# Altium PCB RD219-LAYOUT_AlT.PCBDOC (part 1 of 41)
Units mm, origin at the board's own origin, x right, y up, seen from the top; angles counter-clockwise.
Board outline 209.75 x 159.97 mm, 2 copper layers (TOP, BOTTOM), stack 0 mm thick; 398 components, 199 nets, 1469 pads, 0 vias.
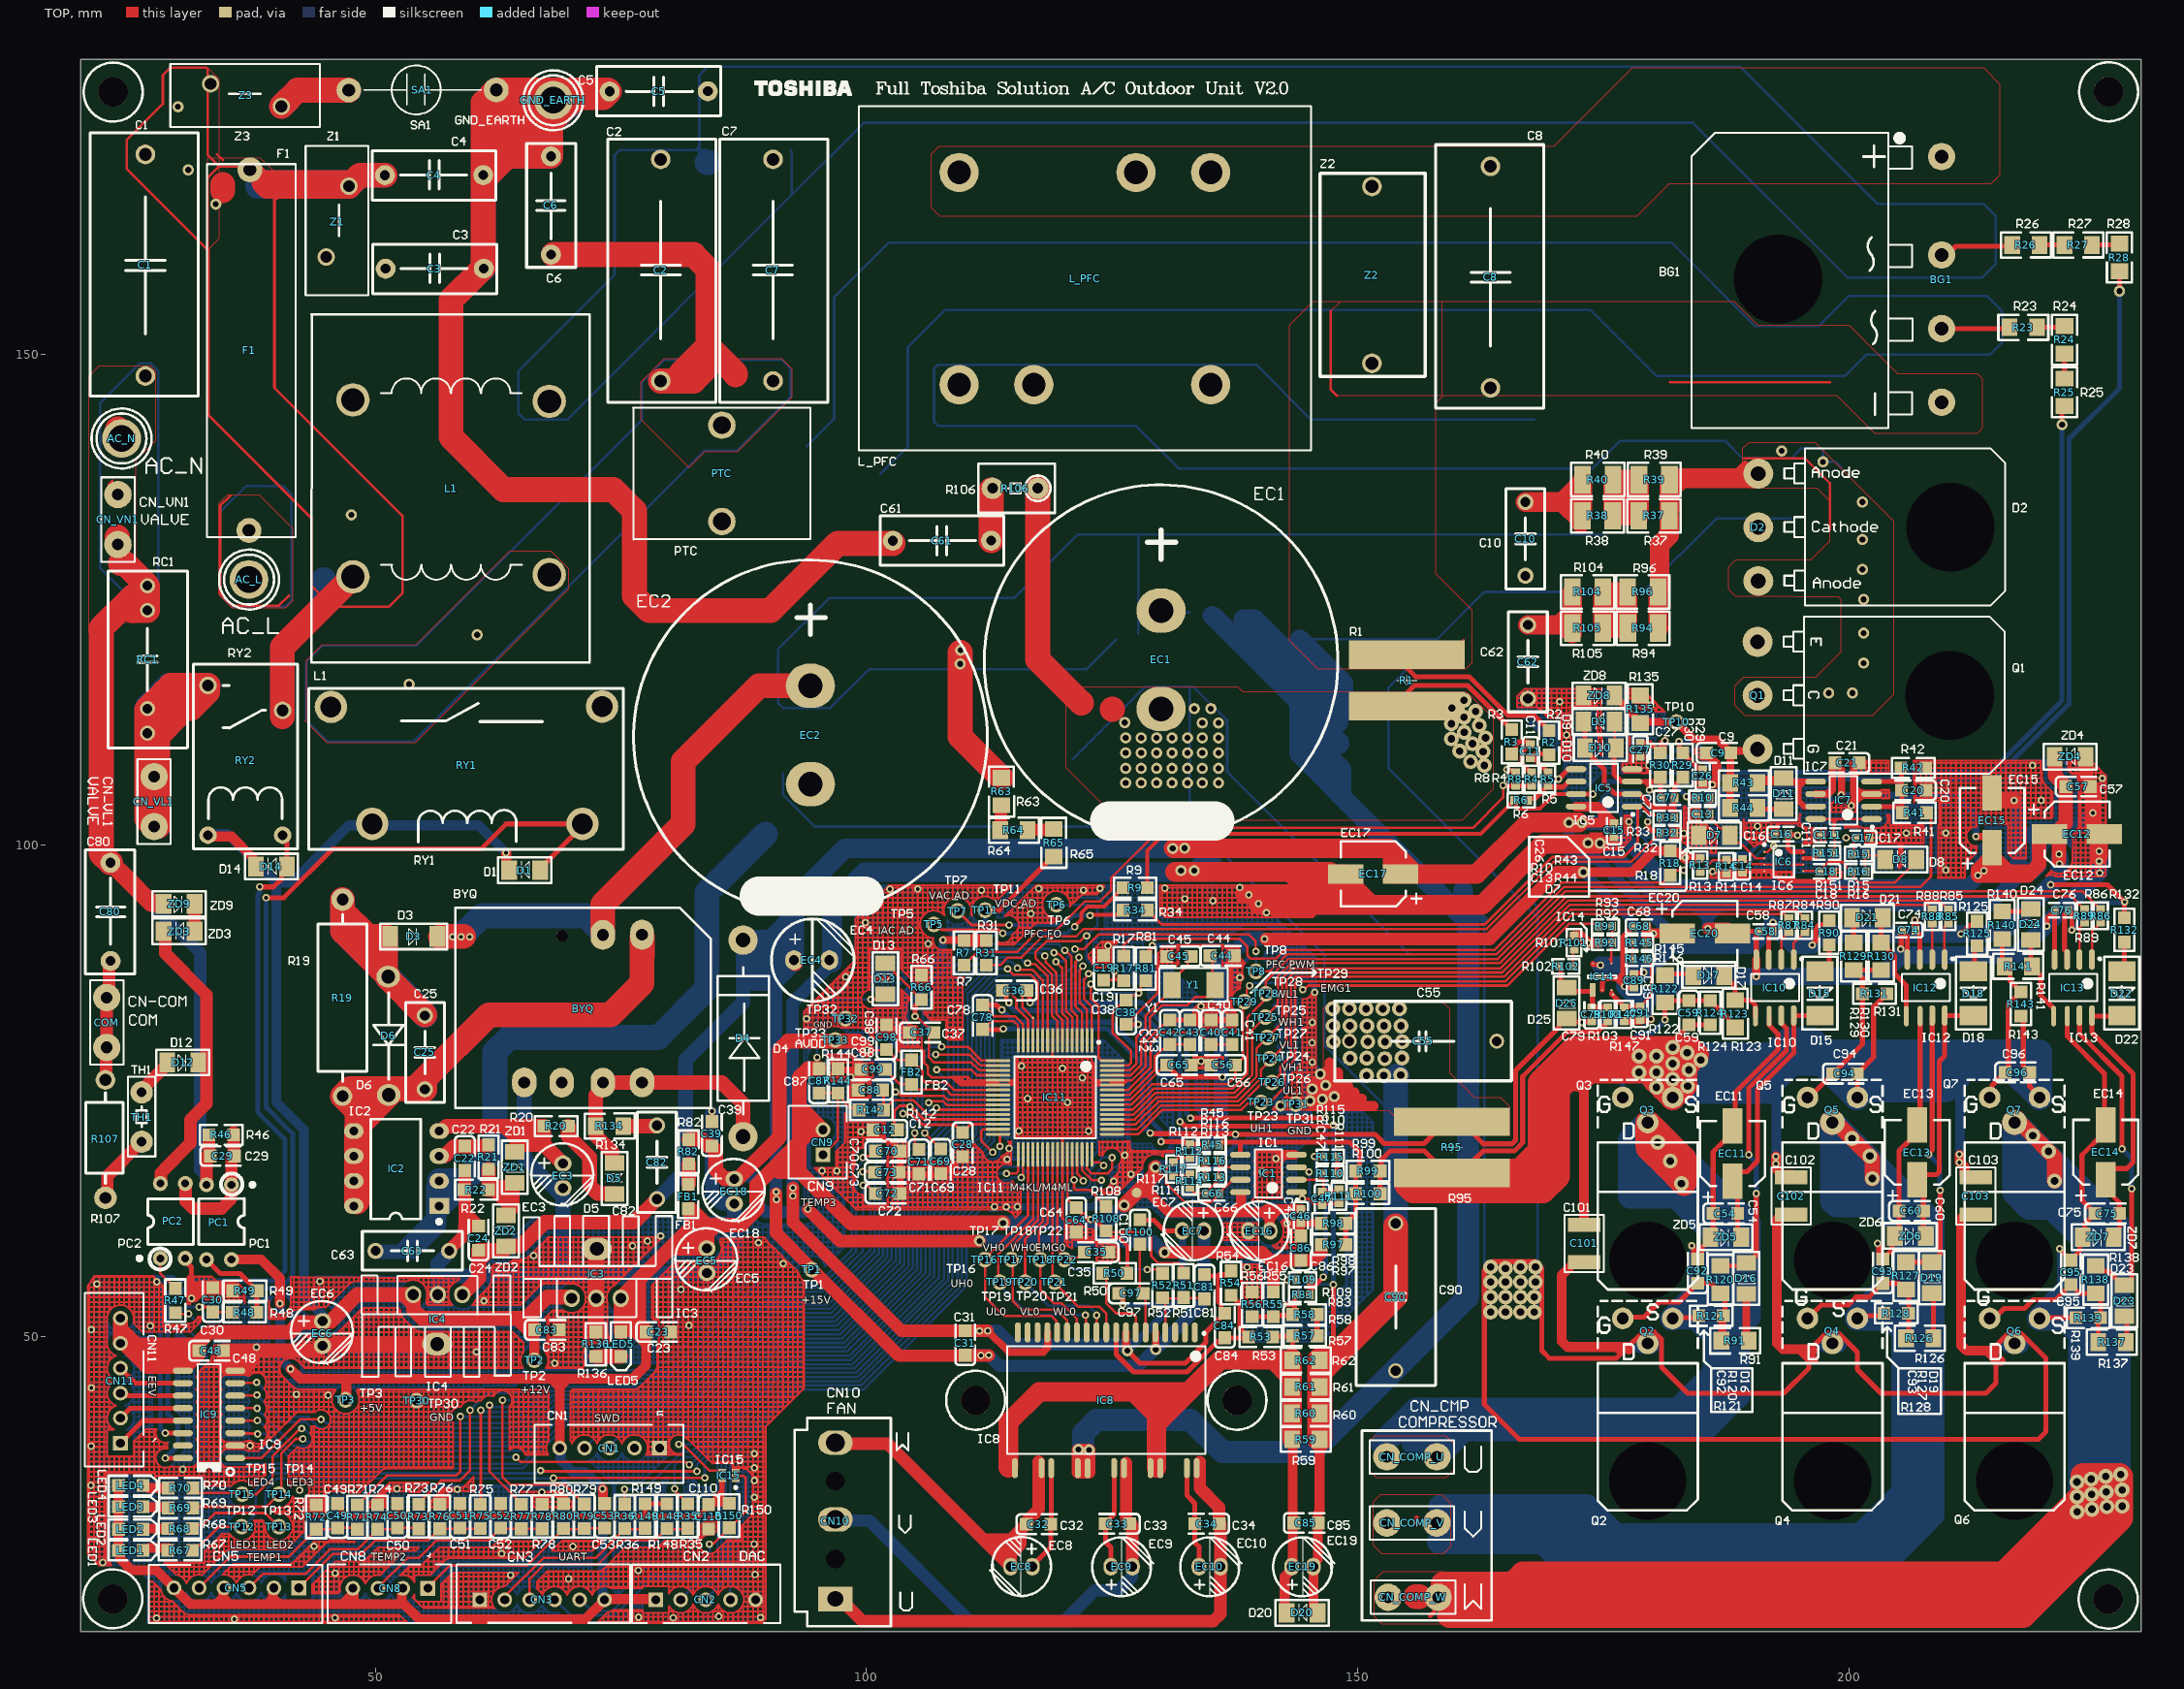
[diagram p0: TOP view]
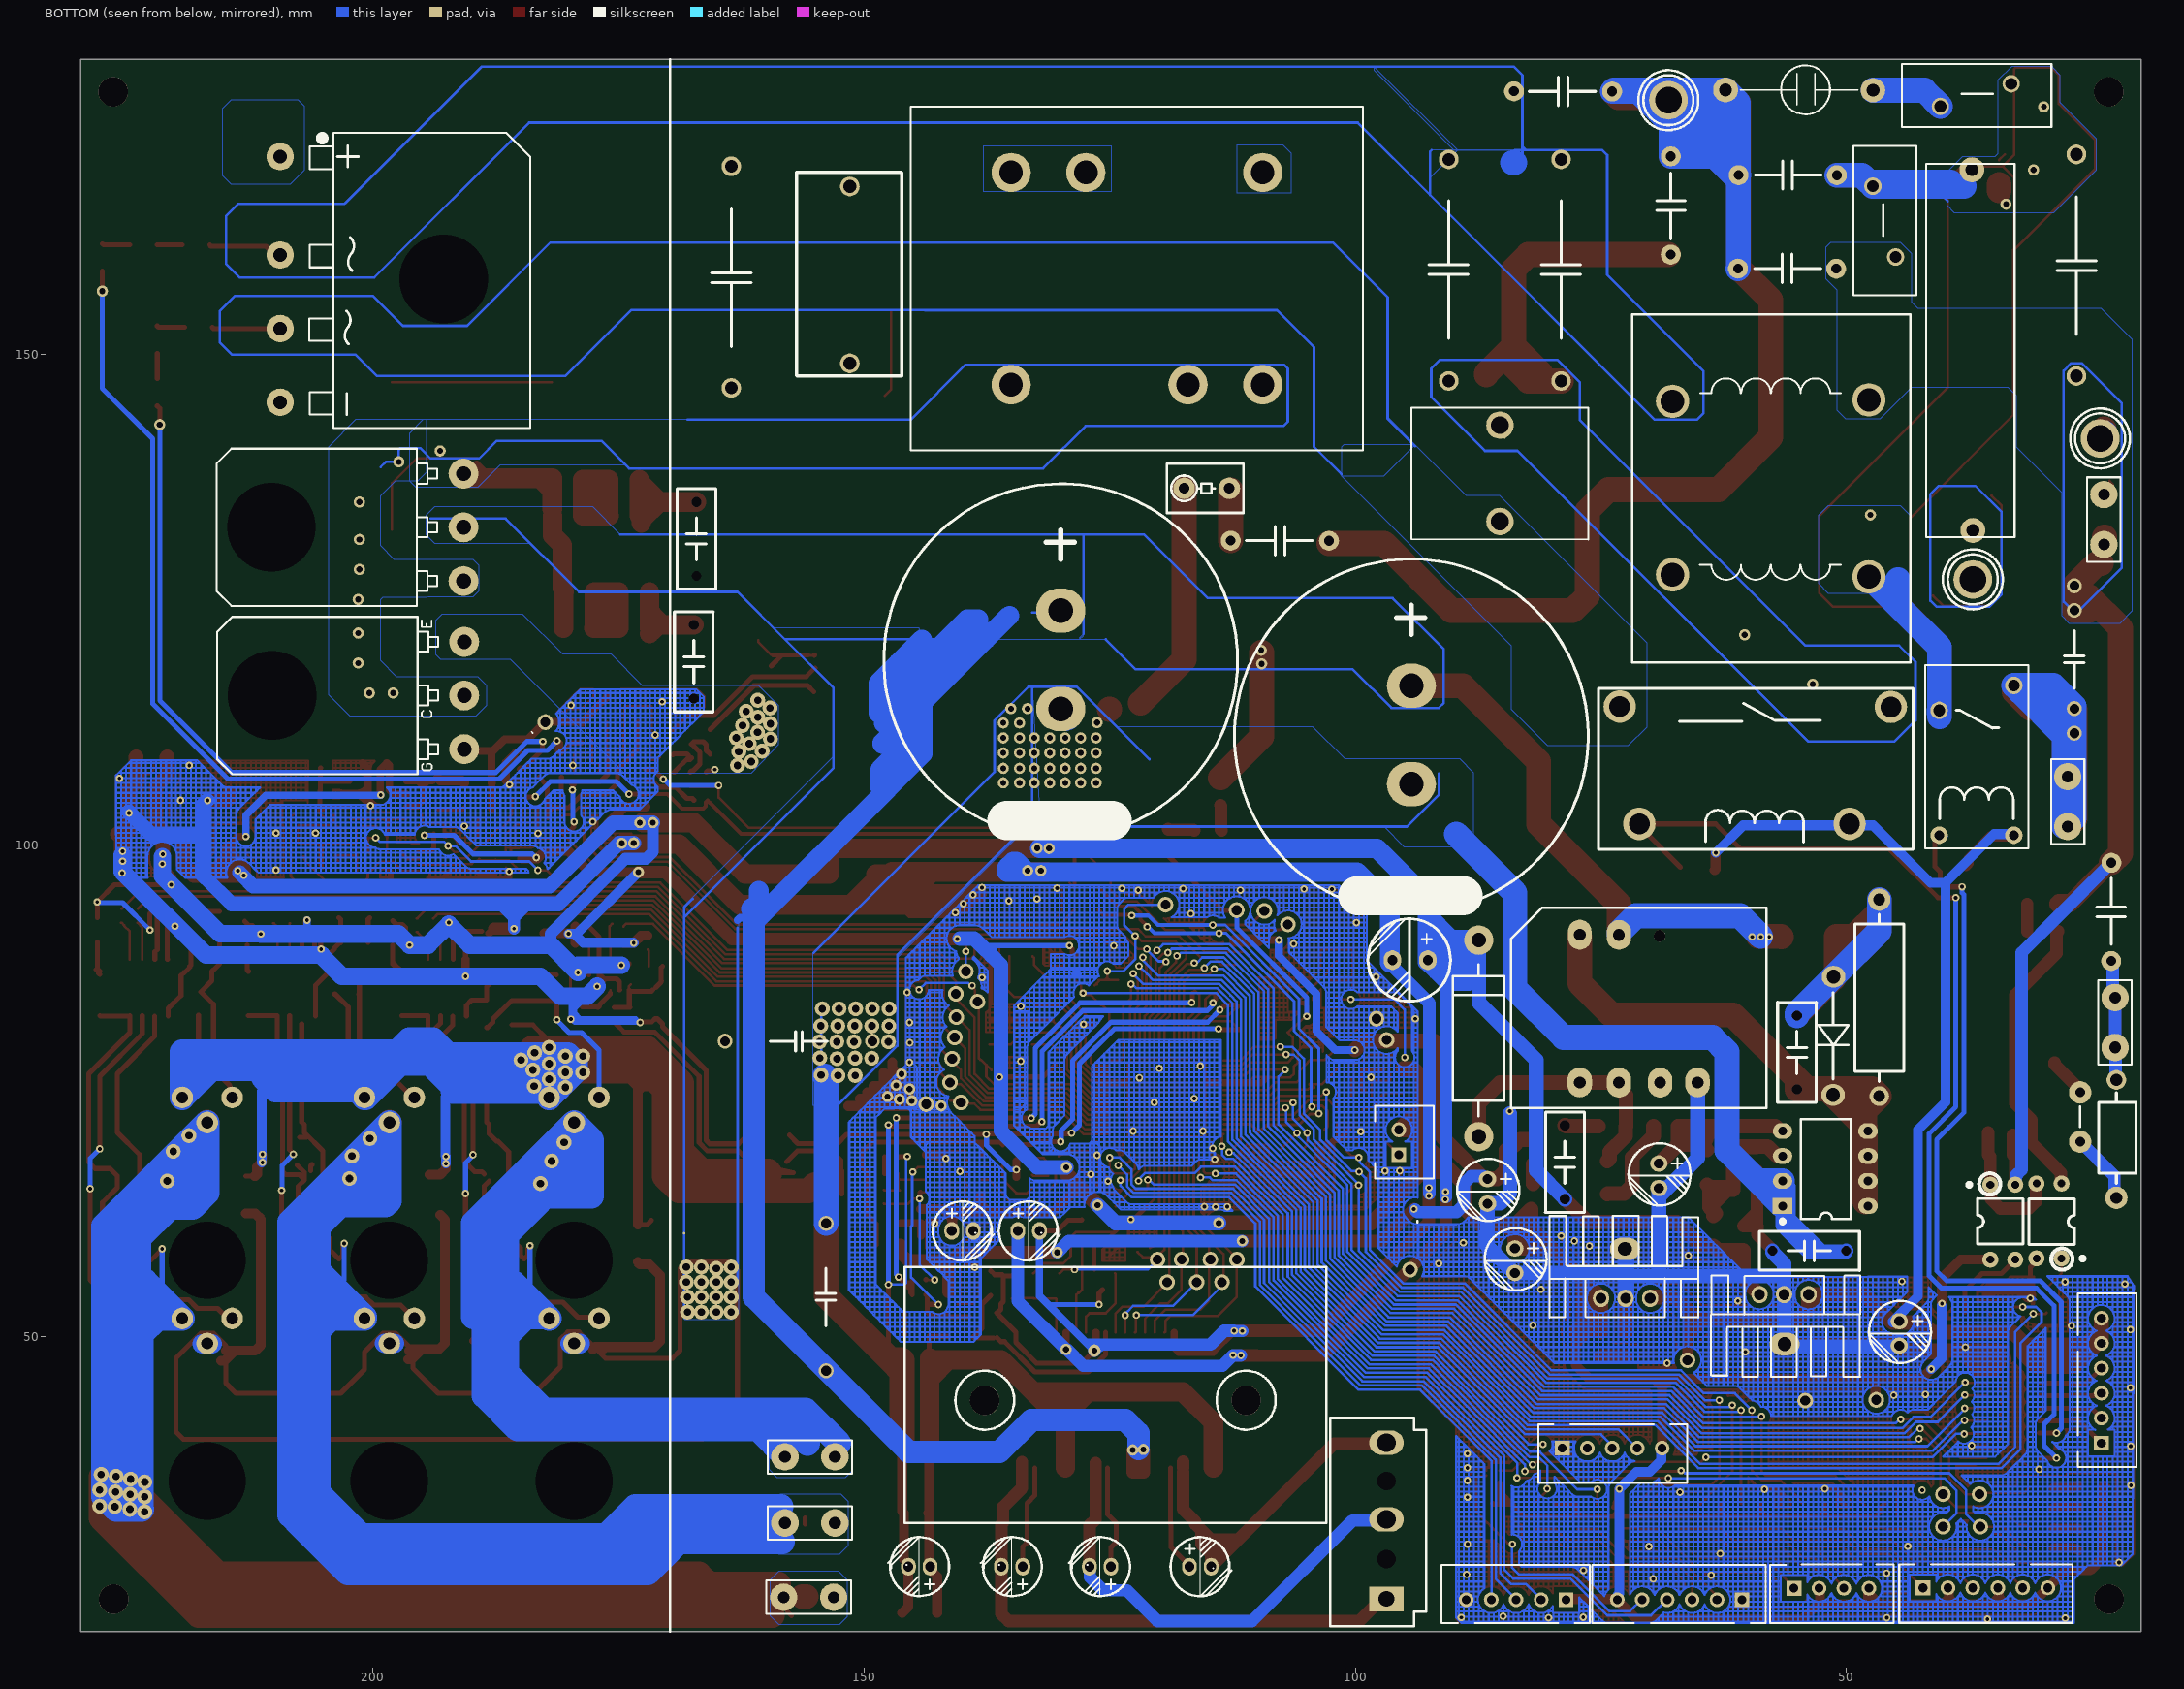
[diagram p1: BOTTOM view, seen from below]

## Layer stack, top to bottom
Top Solder: solder mask 0.0102, Solder Resist, Dk 3.5
TOP: signal copper (thickness not stored)
BOTTOM: signal copper (thickness not stored)
Bottom Solder: solder mask 0.0102, Solder Resist, Dk 3.5

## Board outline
20,20 20,179.971 229.746,179.971 229.746,20

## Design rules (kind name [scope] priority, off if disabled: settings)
AssemblyTestPointUsage [All] p0: scope1count=1 scope1_0_kind=Board scope1_0_value=Board scope2count=1 scope2_0_kind=Board scope2_0_value=Board commentlength=0
AssemblyTestpoint [All] p0: scope1count=1 scope1_0_kind=Board scope1_0_value=Board scope2count=1 scope2_0_kind=Board scope2_0_value=Board commentlength=0
Clearance [All] p0: scope1count=1 scope1_0_kind=Board scope1_0_value=Board scope2count=1 scope2_0_kind=Board scope2_0_value=Board commentlength=0 gap=0.15
Clearance [All] p1: gap=0.15 ignorepadtopadclearanceinfootprint=TRUE except(0.2: SMDPad-Fill SMDPad-Poly SMDPad-Region THPad-Fill THPad-Poly THPad-Region; 0.3: Arc-Hole Track-Hole SMDPad-Hole THPad-Hole Via-Hole Fill-Hole Poly-Hole Region-Hole Text-Hole)
ComponentClearance [All] p0: scope1count=1 scope1_0_kind=Board scope1_0_value=Board scope2count=1 scope2_0_kind=Board scope2_0_value=Board commentlength=0 gap=0.254 collisioncheckmode=3
DiffPairsRouting [All] p0: scope1count=1 scope1_0_kind=Board scope1_0_value=Board scope2count=1 scope2_0_kind=Board scope2_0_value=Board commentlength=0
FabricationTestPointUsage [All] p0: scope1count=1 scope1_0_kind=Board scope1_0_value=Board scope2count=1 scope2_0_kind=Board scope2_0_value=Board commentlength=0 valid=0 allowmultiple=FALSE
FabricationTestpoint [All] p0: scope1count=1 scope1_0_kind=Board scope1_0_value=Board scope2count=1 scope2_0_kind=Board scope2_0_value=Board commentlength=0 side=3 testpointundercomponent=TRUE minsize=1.016 maxsize=2.54 preferedsize=1.524 minholesize=0 maxholesize=1.016 preferedholesize=0.813 testpointgrid=0.025
FanoutControl Fanout_Default [All] p0: scope1count=1 scope1_0_kind=Board scope1_0_value=Board scope2count=1 scope2_0_kind=Board scope2_0_value=Board commentlength=30 // Fanout_Default (Default Rule)
FanoutControl Fanout_Small [All] p0 off: scope1count=1 scope1_0_kind=Board scope1_0_value=Board scope2count=1 scope2_0_kind=Board scope2_0_value=Board commentlength=84 // Protel DXP Scope 1 Expression Was: (CompPinCount < 5)   Fanout_Small (Default Rule)
FanoutControl Fanout_SOIC [All] p0 off: scope1count=1 scope1_0_kind=Board scope1_0_value=Board scope2count=1 scope2_0_kind=Board scope2_0_value=Board commentlength=71 // Protel DXP Scope 1 Expression Was: IsSOIC   Fanout_SOIC (Default Rule)
FanoutControl Fanout_LCC [All] p0 off: scope1count=1 scope1_0_kind=Board scope1_0_value=Board scope2count=1 scope2_0_kind=Board scope2_0_value=Board commentlength=69 // Protel DXP Scope 1 Expression Was: IsLCC   Fanout_LCC (Default Rule)
FanoutControl Fanout_BGA [All] p0 off: scope1count=1 scope1_0_kind=Board scope1_0_value=Board scope2count=1 scope2_0_kind=Board scope2_0_value=Board commentlength=69 // Protel DXP Scope 1 Expression Was: IsBGA   Fanout_BGA (Default Rule)
Height [All] p0: scope1count=1 scope1_0_kind=Board scope1_0_value=Board scope2count=1 scope2_0_kind=Board scope2_0_value=Board commentlength=0
HoleSize [All] p0: scope1count=1 scope1_0_kind=Board scope1_0_value=Board scope2count=1 scope2_0_kind=Board scope2_0_value=Board commentlength=0 absolutevalues=TRUE maxlimit=100 minlimit=0.001 maxpercent=80.000 minpercent=20.000
HoleSize [All] p1: absolutevalues=TRUE maxlimit=100 minlimit=0.001 maxpercent=80.000 minpercent=20.000
HoleToHoleClearance [All] p0: scope1count=1 scope1_0_kind=Board scope1_0_value=Board scope2count=1 scope2_0_kind=Board scope2_0_value=Board commentlength=0
HoleToHoleClearance [All] p1: gap=0.4 allowstackedmicrovias=FALSE
LayerPairs [All] p0: scope1count=1 scope1_0_kind=Board scope1_0_value=Board scope2count=1 scope2_0_kind=Board scope2_0_value=Board commentlength=0 enforce=TRUE
MinimumSolderMaskSliver [All] p0: scope1count=1 scope1_0_kind=Board scope1_0_value=Board scope2count=1 scope2_0_kind=Board scope2_0_value=Board commentlength=0
MinimumSolderMaskSliver [All] p1: minsoldermaskwidth=0.1
NetAntennae [All] p0: scope1count=1 scope1_0_kind=Board scope1_0_value=Board scope2count=1 scope2_0_kind=Board scope2_0_value=Board commentlength=0
NetAntennae [All] p1: netantennaetolerance=100
PasteMaskExpansion [All] p0: scope1count=1 scope1_0_kind=Board scope1_0_value=Board scope2count=1 scope2_0_kind=Board scope2_0_value=Board commentlength=0 expansion=0
PlaneClearance [All] p0: scope1count=1 scope1_0_kind=Board scope1_0_value=Board scope2count=1 scope2_0_kind=Board scope2_0_value=Board commentlength=0 clearance=0.001
PlaneClearance [All] p1: clearance=0.001
PlaneConnect [All] p0: scope1count=1 scope1_0_kind=Board scope1_0_value=Board scope2count=1 scope2_0_kind=Board scope2_0_value=Board commentlength=0 planeconnectstyle=Direct reliefexpansion=0.508 reliefentries=4 reliefconductorwidth=0.254 reliefairgap=0.254
PlaneConnect [All] p1: planeconnectstyle=Direct reliefexpansion=0.508 reliefentries=4 reliefconductorwidth=0.254 reliefairgap=0.254
PolygonConnect [All] p0: scope1count=1 scope1_0_kind=Board scope1_0_value=Board scope2count=1 scope2_0_kind=Board scope2_0_value=Board commentlength=0 connectstyle=Direct reliefconductorwidth=0.254 reliefentries=4 polygonreliefangle="90 Angle"
PolygonConnect [All] p1: connectstyle=Direct reliefconductorwidth=0.254 reliefentries=4 polygonreliefangle="90 Angle" airgapwidth=0.254
RoutingCorners [All] p0: scope1count=1 scope1_0_kind=Board scope1_0_value=Board scope2count=1 scope2_0_kind=Board scope2_0_value=Board commentlength=0 cornerstyle=45-Degree minsetback=2.54 maxsetback=2.54
RoutingLayers [All] p0: scope1count=1 scope1_0_kind=Board scope1_0_value=Board scope2count=1 scope2_0_kind=Board scope2_0_value=Board commentlength=0 top layer=Automatic bottom layer=Automatic
RoutingPriority [All] p0: scope1count=1 scope1_0_kind=Board scope1_0_value=Board scope2count=1 scope2_0_kind=Board scope2_0_value=Board commentlength=0
RoutingTopology [All] p0: scope1count=1 scope1_0_kind=Board scope1_0_value=Board scope2count=1 scope2_0_kind=Board scope2_0_value=Board commentlength=0 topology=Shortest
RoutingVias [All] p0: scope1count=1 scope1_0_kind=Board scope1_0_value=Board scope2count=1 scope2_0_kind=Board scope2_0_value=Board commentlength=0 holewidth=0.1 width=0.1 viastyle="Through Hole" minholewidth=0.001 minwidth=0.001 maxholewidth=100 maxwidth=100
RoutingVias [All] p1: holewidth=0.1 width=0.1 viastyle="Through Hole" minholewidth=0.001 minwidth=0.001 maxholewidth=100 maxwidth=100
ShortCircuit [All] p0: scope1count=1 scope1_0_kind=Board scope1_0_value=Board scope2count=1 scope2_0_kind=Board scope2_0_value=Board commentlength=0 allowed=FALSE
SilkToBoardRegionClearance [All] p0: scope1count=1 scope1_0_kind=Board scope1_0_value=Board scope2count=1 scope2_0_kind=Board scope2_0_value=Board commentlength=0
SilkToSilkClearance [All] p0: scope1count=1 scope1_0_kind=Board scope1_0_value=Board scope2count=1 scope2_0_kind=Board scope2_0_value=Board commentlength=0
SilkToSilkClearance [All] p1: silktosilkclearance=0.001
SilkToSolderMaskClearance [All] p0 off: scope1count=1 scope1_0_kind=Board scope1_0_value=Board scope2count=1 scope2_0_kind=Board scope2_0_value=Board commentlength=44 // Protel DXP Scope 1 Expression Was: IsPad
SilkToSolderMaskClearance [IsPad] p1: minsilkscreentomaskgap=0 clearancetoexposedcopper=TRUE
SolderMaskExpansion [All] p0: scope1count=1 scope1_0_kind=Board scope1_0_value=Board scope2count=1 scope2_0_kind=Board scope2_0_value=Board commentlength=0 expansion=0.001
SolderMaskExpansion [All] p1: expansion=0.001
UnRoutedNet [All] p0: scope1count=1 scope1_0_kind=Board scope1_0_value=Board scope2count=1 scope2_0_kind=Board scope2_0_value=Board commentlength=0
UnpouredPolygon [All] p0: scope1count=1 scope1_0_kind=Board scope1_0_value=Board scope2count=1 scope2_0_kind=Board scope2_0_value=Board commentlength=0
Width [All] p0: scope1count=1 scope1_0_kind=Board scope1_0_value=Board scope2count=1 scope2_0_kind=Board scope2_0_value=Board commentlength=0 maxlimit=1000 minlimit=2539.975 preferedwidth=0
Width [All] p1: maxlimit=1000 minlimit=2539.975 preferedwidth=0 toplayer_minwidth=0 bottomlayer_minwidth=0 minimp=50.000000 maximp=50.000000 favimp=50.000000
22 further rules are at their usual default settings.

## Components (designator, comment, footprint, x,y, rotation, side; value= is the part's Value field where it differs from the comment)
AC_L "PAD4.0MM" PAD4.0MM 37.145,127.061 r90 top
AC_N "PAD4.0MM" PAD4.0MM 24.191,141.412 r0 top
BG1 "BRIDGE_C" BRIDGE_C 201.102,157.589 r0 top
BYQ "KKBYQ4_C" KKBYQ4_C 71.156,83.386 r270 top
C1 "MKP22MM" MKP22MM 26.604,159.012 r270 top
C2 "MKP22MM" MKP22MM 79.055,158.557 r90 top
C3 "C10.0MM" C10.0MM 49.958,161.227 r0 top
C4 "C10.0MM" C10.0MM 49.894,170.74 r0 top
C5 "C10.0MM" C10.0MM 84.944,174.184 r180 top
C6 "C10.0MM" C10.0MM 65.345,159.018 r90 top
C7 "MKP22MM" MKP22MM 90.485,158.557 r90 top
C8 "MKP22MM" MKP22MM 163.51,157.795 r270 top
C9 "SMT-0805-C" SMT-0805-C 185.481,109.408 r0 top
C10 "C7.5MM" C7.5MM 167.066,131.185 r90 top
C11 "SMT-0603-C" SMT-0603-C 167.574,109.597 r270 top
C12 "SMT-0805-C" SMT-0805-C 103.134,71.054 r180 top
C13 "SMT-0603-C" SMT-0603-C 185.1,103.185 r0 top
C14 "SMT-0603-C" SMT-0603-C 189.169,97.916 r90 top
C15 "SMT-0603-C" SMT-0603-C 176.083,101.534 r90 top
C16 "SMT-0603-C" SMT-0603-C 193.101,101.153 r0 top
C17 "SMT-0603-C" SMT-0603-C 201.356,100.772 r180 top
C18 "SMT-0603-C" SMT-0603-C 197.673,97.343 r180 top
C19 "SMT-0805-C" SMT-0805-C 124.148,86.291 r90 top
C20 "SMT-0805-C" SMT-0805-C 207.833,105.598 r180 top
C21 "SMT-0805-C" SMT-0805-C 201.051,108.392 r180 top
C22 "SMT-0805-C" SMT-0805-C 59.116,69.403 r270 top
C23 "SMT-0805-C" SMT-0805-C 77.582,50.48 r0 top
C24 "SMT-0805-C" SMT-0805-C 60.513,58.786 r90 top
C25 "C7.5MM" C7.5MM 55.052,78.928 r90 top
C26 "SMT-0603-C" SMT-0603-C 185.1,107.046 r90 top
C27 "SMT-0603-C" SMT-0603-C 178.75,109.724 r270 top
C28 "SMT-0805-C" SMT-0805-C 109.789,70.8 r270 top
C29 "SMT-0805-C" SMT-0805-C 33.208,68.387 r0 top
C30 "SMT-0805-C" SMT-0805-C 33.462,52.512 r90 top
C31 "SMT-0805-C" SMT-0805-C 110.043,48.118 r90 top
C32 "SMT-0805-C" SMT-0805-C 116.266,30.922 r0 top
C33 "SMT-0805-C" SMT-0805-C 126.801,30.965 r180 top
C34 "SMT-0805-C" SMT-0805-C 135.899,30.968 r180 top
C35 "SMT-0805-C" SMT-0805-C 124.648,58.608 r180 top
C36 "SMT-0805-C" SMT-0805-C 116.317,85.227 r180 top
C37 "SMT-0805-C" SMT-0805-C 104.379,80.96 r0 top
C38 "SMT-0805-C" SMT-0805-C 126.426,81.773 r90 top
C39 "SMT-0805-C" SMT-0805-C 84.262,69.403 r90 top
C40 "SMT-0805-C" SMT-0805-C 135.062,82.23 r270 top
C41 "SMT-0805-C" SMT-0805-C 137.221,82.23 r270 top
C42 "SMT-0805-C" SMT-0805-C 130.871,82.23 r270 top
C43 "SMT-0805-C" SMT-0805-C 132.903,82.23 r270 top
C44 "SMT-0805-C" SMT-0805-C 134.96,88.759 r0 top
C45 "SMT-0805-C" SMT-0805-C 133.03,88.707 r180 top
C46 "SMT-0603-C" SMT-0603-C 144.206,62.291 r270 top
C47 "SMT-0603-C" SMT-0603-C 146.365,64.069 r270 top
C48 "SMT-0805-C" SMT-0805-C 32.065,48.575 r0 top
C49 "SMT-0805-C" SMT-0805-C 46.162,30.541 r90 top
C50 "SMT-0805-C" SMT-0805-C 52.258,30.541 r90 top
C51 "SMT-0805-C" SMT-0805-C 58.618,30.535 r90 top
C52 "SMT-0805-C" SMT-0805-C 62.762,30.535 r90 top
C53 "SMT-0805-C" SMT-0805-C 73.34,30.541 r90 top
C54 "SMT-0805-C" SMT-0805-C 186.167,62.545 r0 top
C55 "C15.0+10.0mm" C15.0+10.0mm 156.645,80.071 r0 top
C56 "SMT-0805-C" SMT-0805-C 137.551,77.658 r180 top
C57 "SMT-0805-C" SMT-0805-C 222.057,105.979 r0 top
C58 "SMT-0603-C" SMT-0603-C 191.512,91.247 r180 top
C59 "SMT-0805-C" SMT-0805-C 183.703,84.211 r270 top
C60 "SMT-0805-C" SMT-0805-C 205.09,62.799 r0 top
C61 "C10.0MM" C10.0MM 113.773,128.464 r180 top
C62 "C7.5MM" C7.5MM 167.32,118.679 r270 top
C63 "C7.5MM" C7.5MM 53.782,58.735 r180 top
C64 "SMT-0805-C" SMT-0805-C 121.346,63.129 r270 top
C65 "SMT-0805-C" SMT-0805-C 130.541,77.658 r0 top
C66 "SMT-0603-C" SMT-0603-C 135.189,64.577 r0 top
C68 "SMT-0603-C" SMT-0603-C 178.685,91.755 r0 top
C69 "SMT-0805-C" SMT-0805-C 107.55,69.097 r270 top
C70 "SMT-0805-C" SMT-0805-C 100.899,68.895 r0 top
C71 "SMT-0805-C" SMT-0805-C 105.334,69.066 r270 top
C72 "SMT-0805-C" SMT-0805-C 100.899,64.577 r0 top
C73 "SMT-0805-C" SMT-0805-C 100.823,66.736 r0 top
C74 "SMT-0603-C" SMT-0603-C 206.055,91.374 r180 top
C75 "SMT-0805-C" SMT-0805-C 225.029,62.545 r0 top
C76 "SMT-0603-C" SMT-0603-C 221.611,93.406 r180 top
C77 "SMT-0603-C" SMT-0603-C 181.544,104.836 r0 top
C78 "SMT-0805-C" SMT-0805-C 111.821,83.754 r270 top
C79 "SMT-0603-C" SMT-0603-C 173.797,82.803 r90 top
C80 "C10.0MM" C10.0MM 25.594,99.328 r270 top
C81 "SMT-0805-C" SMT-0805-C 134.394,56.322 r270 top
C82 "C7.5MM" C7.5MM 78.674,67.752 r90 top
C83 "SMT-0805-C" SMT-0805-C 66.235,50.698 r0 top
C84 "SMT-0805-C" SMT-0805-C 136.463,49.893 r90 top
C85 "SMT-0805-C" SMT-0805-C 143.495,31.049 r0 top
C86 "SMT-0805-C" SMT-0805-C 144.206,57.77 r90 top
C87 "SMT-0805-C" SMT-0805-C 95.184,74.788 r90 top
C88 "SMT-0805-C" SMT-0805-C 101.64,75.097 r180 top
C89 "SMT-0603-C" SMT-0603-C 178.115,86.232 r90 top
C90 "C15.0+10.0mm" C15.0+10.0mm 153.858,54.036 r270 top
C91 "SMT-0603-C" SMT-0603-C 178.75,82.93 r90 top
C92 "SMT-0805-C" SMT-0805-C 184.592,55.433 r90 top
C93 "SMT-0805-C" SMT-0805-C 203.437,55.414 r90 top
C94 "SMT-0805-C" SMT-0805-C 198.359,76.769 r0 top
C95 "SMT-0805-C" SMT-0805-C 222.565,55.306 r90 top
C96 "SMT-0805-C" SMT-0805-C 215.885,76.896 r0 top
C97 "SMT-0805-C" SMT-0805-C 125.664,54.417 r0 top
C98 "SMT-0805-C" SMT-0805-C 102.042,79.233 r90 top
C99 "SMT-0805-C" SMT-0805-C 101.903,77.204 r180 top
C100 "SMT-0805-C" SMT-0805-C 127.823,61.91 r270 top
C101 "1812" 1812 173.035,59.497 r90 top
C102 "1812" 1812 194.117,64.323 r90 top
C103 "1812" 1812 212.913,64.323 r90 top
C110 "SMT-0805-C" SMT-0805-C 83.936,32.917 r270 top
C111 "SMT-0603-C" SMT-0603-C 197.862,101.026 r0 top
CN1 "XH2.54/5P" XH2.54/5P 78.928,38.669 r180 top
CN2 "XH2.54/5P" XH2.54/5P 78.547,23.241 r0 top
CN3 "XH2.54/6P" XH2.54/6P 60.64,23.241 r0 top
CN5 "XH2.54/6P" XH2.54/6P 42.225,24.445 r180 top
CN8 "XH2.54/4P" XH2.54/4P 55.349,24.397 r180 top
CN9 "XH2.54/2P" XH2.54/2P 95.565,68.514 r90 top
CN10 "HDR1X5H" HDR1X5H 96.835,23.316 r90 top
CN11 "XH2.54/6P" XH2.54/6P 24.064,39.177 r90 top
CN_COMP_U "PAD250" PAD250 155.509,37.78 r90 top
CN_COMP_V "PAD250" PAD250 155.509,31.049 r90 top
CN_COMP_W "PAD250" PAD250 155.636,23.493 r90 top
CN_VL1 "PAD250" PAD250 27.493,104.455 r180 top
CN_VN1 "PAD250" PAD250 23.81,133.157 r180 top
COM "PAD250" PAD250 22.667,81.976 r180 top
D1 "1N4148" 1N4148 65.212,97.47 r180 top
D2 "TRS24N65FB_C" TRS24N65FB_C 210.119,132.443 r180 top
D3 "CMF02A" CMF02A 53.928,90.734 r0 top
D4 "D20.0mm" D20.0mm 87.437,70.358 r0 top
D5 "1N4148" 1N4148 74.356,66.101 r270 top
D6 "D12.0MM" D12.0MM 51.369,86.61 r270 top
D7 "1N4148" 1N4148 186.297,101.026 r0 top
D8 "1N4148" 1N4148 205.255,98.57 r180 top
D9 "1N4148" 1N4148 174.559,112.583 r180 top
D10 "1N4148" 1N4148 174.686,109.916 r0 top
D11 "1N4148" 1N4148 193.355,105.271 r90 top
D12 "1N4148" 1N4148 30.414,77.912 r0 top
D13 "1N4148" 1N4148 101.915,86.421 r270 top
D14 "1N4148" 1N4148 39.431,97.851 r180 top
D15 "DIODE" DIODE 197.419,87.564 r270 top
D16 "1N4148" 1N4148 189.545,55.941 r90 top
D17 "1N4148" 1N4148 185.73,86.799 r0 top
D18 "DIODE" DIODE 213.04,87.564 r270 top
D19 "1N4148" 1N4148 208.414,56.014 r90 top
D20 "1N4148" 1N4148 144.333,21.905 r180 top
D21 "1N4148" 1N4148 201.864,92.644 r0 top
D22 "DIODE" DIODE 228.153,87.564 r270 top
D23 "1N4148" 1N4148 228.026,53.655 r90 top
D24 "1N4148" 1N4148 218.501,91.955 r270 top
D25 "1N4148" 1N4148 171.257,83.954 r90 top
EC1 "RB0.8-10-36" RB0.8-10-36 129.982,123.886 r270 top
EC2 "RB0.8-10-36" RB0.8-10-36 94.295,116.233 r270 top
EC3 "E2.5-6.3MM" E2.5-6.3MM 69.105,68.895 r180 top
EC4 "E3.7-8.4MM" E3.7-8.4MM 94.422,88.326 r270 top
EC5 "E2.5-6.3MM" E2.5-6.3MM 83.754,60.259 r180 top
EC6 "E2.5-6.3MM" E2.5-6.3MM 44.638,52.853 r180 top
EC7 "E2-6MM" E2-6MM 133.241,60.767 r90 top
EC8 "E2-6MM" E2-6MM 115.774,26.604 r90 top
EC9 "E2-6MM" E2-6MM 125.961,26.604 r270 top
EC10 "E2-6MM" E2-6MM 134.935,26.604 r270 top
EC11 "SMD_CAP_6.6_x_6.6" SMD_CAP_6.6_x_6.6 188.148,68.641 r90 top
EC12 "SMD_CAP_6.6_x_6.6" SMD_CAP_6.6_x_6.6 223.2,101.153 r0 top
EC13 "SMD_CAP_6.6_x_6.6" SMD_CAP_6.6_x_6.6 206.944,68.762 r90 top
EC14 "SMD_CAP_6.6_x_6.6" SMD_CAP_6.6_x_6.6 226.121,68.768 r90 top
EC15 "SMD_CAP_6.6_x_6.6" SMD_CAP_6.6_x_6.6 214.564,102.544 r90 top
EC16 "E2-6MM" E2-6MM 139.972,60.767 r90 top
EC17 "SMD_CAP_6.6_x_6.6" SMD_CAP_6.6_x_6.6 151.572,97.089 r180 top
EC18 "E2.5-6.3MM" E2.5-6.3MM 86.541,67.313 r180 top
EC19 "E2-6MM" E2-6MM 144.376,26.604 r270 top
EC20 "SMD_CAP_6.6_x_6.6" SMD_CAP_6.6_x_6.6 185.34,91.046 r0 top
F1 "FUSE30A/250VAC" FUSE30A/250VAC 37.195,150.346 r90 top
FB1 "SMT-0805-R" SMT-0805-R 81.846,65.499 r270 top
FB2 "SMT-0805-R" SMT-0805-R 104.582,78.166 r270 top
GND_EARTH "PAD4.0MM" PAD4.0MM 68.133,175.829 r0 top
IC1 "SOP-8" SOP-8 140.904,66.609 r180 top
IC2 "DIP8" DIP8 56.513,63.307 r180 top
IC3 "TO220_heat_sink_C" TO220_heat_sink_C 72.504,52.682 r180 top
IC4 "TO220_heat_sink_C" TO220_heat_sink_C 56.349,55.517 r0 top
IC5 "SOP-8" SOP-8 175.067,105.852 r180 top
IC6 "SSOP8" SSOP8 193.355,98.359 r0 top
IC7 "SOP-8" SOP-8 199.451,104.582 r180 top
IC8 "P-SSOP30_C" P-SSOP30_C 124.406,43.537 r270 top
IC9 "SOP16" SOP16 35.748,37.653 r90 top
IC10 "SOP-8_-1" SOP-8_-1 192.466,85.532 r270 top
IC11 "LQFP64_M" LQFP64_M 119.187,74.356 r270 top
IC12 "SOP-8_-1" SOP-8_-1 207.833,85.532 r270 top
IC13 "SOP-8_-1" SOP-8_-1 222.819,85.532 r270 top
IC14 "FP-SSOP5-IPC_A" FP-SSOP5-IPC_A 174.874,86.628 r90 top
IC15 "SOTFL50P160X60-5N" SOTFL50P160X60-5N 86,35.875 r180 top
L1 "FT-4-15C" FT-4-15C 57.719,136.332 r180 top
L_PFC "PFC_INDUCTANCE_C" PFC_INDUCTANCE_C 122.228,157.673 r0 top
LED1 "LED-0805" LED-0805 23.861,28.255 r0 top
LED2 "LED-0805" LED-0805 23.861,30.414 r0 top
LED3 "LED-0805" LED-0805 23.861,32.7 r0 top
LED4 "LED-0805" LED-0805 23.861,34.859 r0 top
LED5 "LED-0805" LED-0805 74.991,50.48 r270 top
PC1 "TLP521" TLP521 32.065,66.228 r0 top
PC2 "TLP521" TLP521 31.43,57.211 r180 top
PTC "PTC__12X20_" PTC__12X20_ 85.278,137.856 r180 top
Q1 "TO-3P_C" TO-3P_C 210.046,115.327 r180 top
Q2 "TK20A60W5_C" TK20A60W5_C 179.512,50.845 r0 top
Q3 "TK20A60W5_C" TK20A60W5_C 179.512,73.324 r0 top
Q4 "TK20A60W5_C" TK20A60W5_C 198.308,50.845 r0 top
Q5 "TK20A60W5_C" TK20A60W5_C 198.308,73.324 r0 top
Q6 "TK20A60W5_C" TK20A60W5_C 216.85,50.845 r0 top
Q7 "TK20A60W5_C" TK20A60W5_C 216.85,73.324 r0 top
R1 "FCSL110R010FER" FCSL110R010FER 155.005,116.788 r270 top
R2 "SMT-0805-R" SMT-0805-R 169.479,111.694 r270 top
R3 "SMT-0805-R" SMT-0805-R 165.669,111.77 r270 top
R4 "SMT-0603-R" SMT-0603-R 167.701,106.741 r270 top
R5 "SMT-0603-R" SMT-0603-R 169.352,106.741 r270 top
R6 "SMT-0603-R" SMT-0603-R 166.62,104.582 r180 top
R7 "SMT-0805-R" SMT-0805-R 109.916,90.307 r270 top
R8 "SMT-0603-R" SMT-0603-R 166.05,106.741 r90 top
R9 "SMT-0805-R" SMT-0805-R 128.585,95.692 r180 top
R10 "SMT-0603-R" SMT-0603-R 185.1,104.836 r180 top
R13 "SMT-0603-R" SMT-0603-R 184.846,97.978 r90 top
R14 "SMT-0603-R" SMT-0603-R 187.506,97.83 r90 top
R15 "SMT-0603-R" SMT-0603-R 200.975,99.121 r0 top
R16 "SMT-0603-R" SMT-0603-R 200.975,97.343 r180 top
R17 "SMT-0805-R" SMT-0805-R 126.174,88.726 r270 top
R18 "SMT-0805-R" SMT-0805-R 181.798,96.962 r90 top
R19 "R20.0MM" R20.0MM 46.67,94.483 r180 top
R20 "SMT-0805-R" SMT-0805-R 69.657,71.435 r180 top
R21 "SMT-0805-R" SMT-0805-R 61.529,69.53 r270 top
R22 "SMT-0805-R" SMT-0805-R 59.04,64.958 r0 top
R23 "SMT-1206-R" SMT-1206-R 217.739,152.715 r0 top
R24 "SMT-1206-R" SMT-1206-R 221.93,151.442 r270 top
R25 "SMT-1206-R" SMT-1206-R 221.93,146.108 r270 top
R26 "SMT-1206-R" SMT-1206-R 217.993,161.097 r0 top
R27 "SMT-1206-R" SMT-1206-R 223.327,161.097 r0 top
R28 "SMT-1206-R" SMT-1206-R 227.518,159.824 r270 top
R29 "SMT-0805-R" SMT-0805-R 183.068,109.408 r270 top
R30 "SMT-0805-R" SMT-0805-R 180.782,109.408 r270 top
R31 "SMT-0805-R" SMT-0805-R 112.202,90.307 r270 top
R32 "SMT-0603-R" SMT-0603-R 181.479,101.28 r0 top
R33 "SMT-0603-R" SMT-0603-R 181.479,102.804 r180 top
R34 "SMT-0805-R" SMT-0805-R 128.585,93.406 r180 top
R35 "SMT-0805-R" SMT-0805-R 81.813,32.997 r270 top
R36 "SMT-0805-R" SMT-0805-R 75.403,32.969 r270 top
R37 "SMT-1210-R" SMT-1210-R 180.147,133.538 r0 top
R38 "SMT-1210-R" SMT-1210-R 174.406,133.538 r0 top
R39 "SMT-1210-R" SMT-1210-R 180.173,137.221 r0 top
R40 "SMT-1210-R" SMT-1210-R 174.432,137.221 r0 top
R41 "SMT-0805-R" SMT-0805-R 207.909,103.312 r180 top
R42 "SMT-0805-R" SMT-0805-R 207.782,107.884 r180 top
R43 "SMT-1206-R" SMT-1206-R 189.291,106.36 r0 top
R44 "SMT-1206-R" SMT-1206-R 189.291,103.82 r0 top
R45 "SMT-0603-R" SMT-0603-R 135.189,69.53 r0 top
R46 "SMT-0805-R" SMT-0805-R 35.57,70.546 r180 top
R47 "SMT-0805-R" SMT-0805-R 29.652,52.436 r90 top
R48 "SMT-0805-R" SMT-0805-R 35.466,52.475 r0 top
R49 "SMT-0805-R" SMT-0805-R 35.494,54.671 r0 top
R50 "SMT-0805-R" SMT-0805-R 124.02,56.462 r0 top
R51 "SMT-0805-R" SMT-0805-R 132.276,53.988 r90 top
R52 "SMT-0805-R" SMT-0805-R 130.119,53.959 r90 top
R53 "SMT-0805-R" SMT-0805-R 141.361,49.972 r180 top
R54 "SMT-0805-R" SMT-0805-R 137.094,54.214 r90 top
R55 "SMT-0805-R" SMT-0805-R 141.412,54.544 r270 top
R56 "SMT-0805-R" SMT-0805-R 139.253,52.055 r90 top
R57 "SMT-0805-R" SMT-0805-R 143.368,50.099 r0 top
R58 "SMT-0805-R" SMT-0805-R 145.857,52.258 r180 top
R59 "SMT-1206-R" SMT-1206-R 144.714,39.558 r180 top
R60 "SMT-1206-R" SMT-1206-R 144.705,42.204 r180 top
R61 "SMT-1206-R" SMT-1206-R 144.714,44.892 r180 top
R62 "SMT-1206-R" SMT-1206-R 144.717,47.596 r180 top
R63 "SMT-1206-R" SMT-1206-R 113.726,105.471 r90 top
R64 "SMT-1206-R" SMT-1206-R 114.996,101.534 r180 top
R65 "SMT-1206-R" SMT-1206-R 119.06,100.261 r90 top
R66 "SMT-0805-R" SMT-0805-R 105.598,86.802 r270 top
R67 "SMT-0805-R" SMT-0805-R 28.89,28.255 r0 top
R68 "SMT-0805-R" SMT-0805-R 28.877,30.478 r0 top
R69 "SMT-0805-R" SMT-0805-R 28.941,32.573 r0 top
R70 "SMT-0805-R" SMT-0805-R 28.941,34.605 r0 top
R71 "SMT-0805-R" SMT-0805-R 48.194,30.414 r90 top
R72 "SMT-0805-R" SMT-0805-R 44.003,32.903 r270 top
R73 "SMT-0805-R" SMT-0805-R 54.417,30.465 r90 top
R74 "SMT-0805-R" SMT-0805-R 50.226,32.903 r270 top
R75 "SMT-0805-R" SMT-0805-R 60.697,30.475 r90 top
R76 "SMT-0805-R" SMT-0805-R 56.567,32.95 r270 top
R77 "SMT-0805-R" SMT-0805-R 64.861,30.464 r90 top
R78 "SMT-0805-R" SMT-0805-R 66.99,32.954 r270 top
R79 "SMT-0805-R" SMT-0805-R 71.268,30.493 r90 top
R80 "SMT-0805-R" SMT-0805-R 69.153,32.985 r270 top
R81 "SMT-0805-R" SMT-0805-R 128.431,86.218 r90 top
R82 "SMT-0805-R" SMT-0805-R 81.904,70.067 r270 top
R83 "SMT-0603-R" SMT-0603-R 144.398,54.29 r180 top
R84 "SMT-0603-R" SMT-0603-R 195.514,91.882 r270 top
R85 "SMT-0603-R" SMT-0603-R 210.119,92.771 r270 top
R86 "SMT-0603-R" SMT-0603-R 225.613,92.836 r270 top
R87 "SMT-0603-R" SMT-0603-R 193.863,91.882 r270 top
R88 "SMT-0603-R" SMT-0603-R 208.468,92.771 r270 top
R89 "SMT-0603-R" SMT-0603-R 223.962,92.836 r270 top
R90 "SMT-0805-R" SMT-0805-R 197.993,89.861 r90 top
R91 "SMT-1206-R" SMT-1206-R 188.399,49.591 r0 top
R92 "SMT-0603-R" SMT-0603-R 175.194,90.104 r0 top
R93 "SMT-0603-R" SMT-0603-R 175.194,91.755 r180 top
R94 "SMT-1210-R" SMT-1210-R 179.03,122.108 r180 top
R95 "FCSL110R010FER" FCSL110R010FER 159.573,69.276 r270 top
R96 "SMT-1210-R" SMT-1210-R 179.004,125.791 r180 top
R97 "SMT-0805-R" SMT-0805-R 146.289,59.37 r0 top
R98 "SMT-0805-R" SMT-0805-R 148.778,61.529 r180 top
R99 "SMT-0805-R" SMT-0805-R 152.283,66.863 r180 top
R100 "SMT-0805-R" SMT-0805-R 152.277,64.548 r180 top
R101 "SMT-0603-R" SMT-0603-R 172.019,90.104 r90 top
R102 "SMT-0603-R" SMT-0603-R 171.192,87.691 r0 top
R103 "SMT-0603-R" SMT-0603-R 175.448,82.803 r90 top
R104 "SMT-1210-R" SMT-1210-R 173.39,125.791 r180 top
R105 "SMT-1210-R" SMT-1210-R 173.39,122.108 r180 top
R106 "COLOR_RING_RES" COLOR_RING_RES 115.123,136.332 r90 top
R107 "R12.0mm" R12.0mm 22.54,64.134 r0 top
R108 "SMT-0805-R" SMT-0805-R 124.394,60.767 r90 top
R109 "SMT-0603-R" SMT-0603-R 144.398,55.814 r0 top
R110 "SMT-0603-R" SMT-0603-R 147.189,66.609 r180 top
R111 "SMT-0603-R" SMT-0603-R 148.083,64.31 r270 top
R112 "SMT-0603-R" SMT-0603-R 132.901,68.879 r90 top
R113 "SMT-0603-R" SMT-0603-R 135.189,66.228 r0 top
R114 "SMT-0603-R" SMT-0603-R 132.903,65.847 r90 top
R115 "SMT-0603-R" SMT-0603-R 147.211,68.318 r0 top
R116 "SMT-0603-R" SMT-0603-R 135.189,67.879 r0 top
R117 "SMT-0603-R" SMT-0603-R 131.252,67.052 r90 top
R120 "SMT-1206-R" SMT-1206-R 186.905,55.811 r90 top
R121 "SMT-0805-R" SMT-0805-R 187.208,52.131 r180 top
R122 "SMT-1206-R" SMT-1206-R 181.29,85.402 r90 top
R123 "SMT-1206-R" SMT-1206-R 188.402,82.862 r90 top
R124 "SMT-0805-R" SMT-0805-R 185.862,84.211 r270 top
R125 "SMT-0805-R" SMT-0805-R 213.04,89.774 r90 top
R126 "SMT-1206-R" SMT-1206-R 207.195,49.845 r0 top
R127 "SMT-1206-R" SMT-1206-R 205.801,56.192 r90 top
R128 "SMT-0805-R" SMT-0805-R 206.055,52.385 r180 top
R129 "SMT-1206-R" SMT-1206-R 200.467,88.707 r90 top
R130 "SMT-1206-R" SMT-1206-R 203.261,88.704 r90 top
R131 "SMT-0805-R" SMT-0805-R 201.356,84.897 r0 top
R132 "SMT-0805-R" SMT-0805-R 228.026,90.155 r90 top
R134 "SMT-1206-R" SMT-1206-R 73.848,71.435 r180 top
R135 "SMT-1206-R" SMT-1206-R 178.75,113.853 r90 top
R136 "SMT-0805-R" SMT-0805-R 72.451,47.991 r90 top
R137 "SMT-1206-R" SMT-1206-R 226.759,49.458 r0 top
R138 "SMT-1206-R" SMT-1206-R 225.105,55.814 r270 top
R139 "SMT-0805-R" SMT-0805-R 225.593,51.926 r180 top
R140 "SMT-1206-R" SMT-1206-R 215.58,91.879 r90 top
R141 "SMT-1206-R" SMT-1206-R 217.231,87.691 r180 top
R142 "SMT-0805-R" SMT-0805-R 99.248,73.086 r0 top
R143 "SMT-0805-R" SMT-0805-R 217.485,85.1 r270 top
R144 "SMT-0805-R" SMT-0805-R 97.089,77.277 r270 top
R145 "SMT-0603-R" SMT-0603-R 178.685,90.104 r0 top
R146 "SMT-0603-R" SMT-0603-R 178.685,88.453 r180 top
R147 "SMT-0603-R" SMT-0603-R 177.099,82.803 r90 top
R148 "SMT-0805-R" SMT-0805-R 79.677,30.494 r90 top
R149 "SMT-0805-R" SMT-0805-R 77.47,30.508 r90 top
R150 "SMT-0805-R" SMT-0805-R 86.027,30.555 r90 top
R151 "SMT-0603-R" SMT-0603-R 197.735,99.248 r0 top
RC1 "RC15.0+10.0_C" RC15.0+10.0_C 26.818,118.915 r270 top
RY1 "RY-2160" RY-2160 59.243,106.995 r0 top
RY2 "RY-JZC-32F" RY-JZC-32F 31.474,99.686 r0 top
SA1 "Discharge_tube_15.0mm" Discharge_tube_15.0mm 62.304,176.858 r180 top
TH1 "PTC-5.0MM" PTC-5.0MM 26.223,69.846 r90 top
TP1 "TESTPAD" TESTPAD 94.382,56.83 r0 top
TP2 "TESTPAD" TESTPAD 66.15,47.61 r0 top
TP3 "TESTPAD" TESTPAD 46.939,43.576 r0 top
TP5 "TESTPAD" TESTPAD 106.818,91.966 r0 top
TP6 "TESTPAD" TESTPAD 119.314,93.914 r90 top
TP7 "TESTPAD" TESTPAD 109.258,93.285 r90 top
TP8 "TESTPAD" TESTPAD 139.634,87.143 r90 top
TP10 "TESTPAD" TESTPAD 182.433,112.583 r270 top
TP11 "TESTPAD" TESTPAD 112.035,93.406 r0 top
TP12 "TESTPAD" TESTPAD 36.343,30.668 r0 top
TP13 "TESTPAD" TESTPAD 40.153,30.668 r0 top
TP14 "TESTPAD" TESTPAD 40.153,33.97 r0 top
TP15 "TESTPAD" TESTPAD 36.423,33.97 r0 top
TP16 "TESTPAD" TESTPAD 112.006,57.846 r0 top
TP17 "TESTPAD" TESTPAD 114.702,57.846 r0 top
TP18 "TESTPAD" TESTPAD 117.677,57.886 r270 top
TP19 "TESTPAD" TESTPAD 113.599,55.56 r180 top
TP20 "TESTPAD" TESTPAD 116.099,55.56 r0 top
TP21 "TESTPAD" TESTPAD 119.187,55.56 r180 top
TP22 "TESTPAD" TESTPAD 120.121,57.806 r90 top
TP23 "TESTPAD" TESTPAD 140.102,73.848 r0 top
TP24 "TESTPAD" TESTPAD 140.991,78.293 r0 top
TP25 "TESTPAD" TESTPAD 140.558,82.519 r0 top
TP26 "TESTPAD" TESTPAD 141.216,75.88 r0 top
TP27 "TESTPAD" TESTPAD 140.737,80.452 r0 top
TP28 "TESTPAD" TESTPAD 140.61,84.897 r0 top
TP29 "TESTPAD" TESTPAD 138.491,84.095 r180 top
TP30 "TESTPAD" TESTPAD 54.163,43.495 r0 top
TP31 "TESTPAD" TESTPAD 143.636,73.674 r0 top
TP32 "TESTPAD" TESTPAD 97.811,82.357 r0 top
TP33 "TESTPAD" TESTPAD 96.809,80.15 r90 top
Y1 "2010(5025)" 2010(5025) 133.284,85.786 r180 top
Z1 "VA" VA 45.009,159.871 r90 top
Z2 "18MM" 18MM 151.445,158.049 r270 top
Z3 "VA" VA 40.447,175.194 r180 top
ZD1 "1N4148" 1N4148 64.196,67.244 r90 top
ZD2 "1N4148" 1N4148 63.307,60.767 r270 top
ZD3 "1N4148" 1N4148 30.033,91.247 r180 top
ZD4 "1N4148" 1N4148 222.492,109.027 r180 top
ZD5 "1N4148" 1N4148 187.459,60.132 r0 top
ZD6 "1N4148" 1N4148 206.235,60.262 r0 top
ZD7 "1N4148" 1N4148 225.359,60.132 r0 top
ZD8 "1N4148" 1N4148 174.559,115.25 r0 top
ZD9 "1N4148" 1N4148 30.033,94.041 r0 top

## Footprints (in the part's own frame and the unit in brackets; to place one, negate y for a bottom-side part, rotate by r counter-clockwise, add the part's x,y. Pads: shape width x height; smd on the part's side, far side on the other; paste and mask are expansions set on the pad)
1N4148 [mm] "KC00080BKP"
  rect 1.6x2 smd paste-2.203 mask+0: 1(-1.578,0) 2(1.578,0)
18MM [mm] "KC00080BKP"
  round 2 / inner round 0 / far side round 2 hole 1.3 paste-2.203 mask+0: 1(-9,0) 2(9,0)
1812 [mm] "KC00080BKP"
  rect 1.4x3.3 smd paste-3.503 mask+0: 1(-1.9,0) 2(1.9,0)
2010(5025) [mm] "KC00080BKP"
  rect 1.8x2.7 smd paste-2.903 mask+0: 1(-2.2,0) 2(2.2,0)
BRIDGE_C [mil] "KC00080BKP"
  round 110 / inner round 0 / far side round 110 hole 55 paste-118 mask+0: 1(327.5,492) 2(327.5,98) 3(327.5,-197) 4(327.5,-492)
C7.5MM [mm] "KC00080BKP"
  round 1.651 / inner round 0 / far side round 0 hole 1 paste-1.854 mask+0: 1(3.75,0) 2(-3.75,0)
C10.0MM [mil] "KC00080BKP"
  round 80 / inner round 0 / far side round 80 hole 39.37 paste-88 mask+0: 1(436.85,-99.75) 2(43.15,-100.25)
C15.0+10.0mm [mm] "KC00080BKP"
  round 1.524 / inner round 0 / far side round 1.524 hole 1 paste-1.727 mask+0: 1(-7.5,0) 2(7.5,0)
CMF02A [mm] "KC00080BKP"
  rect 1.6x2.1 smd paste-2.303 mask+0: 1(-2.4,0) 2(2.4,0)
COLOR_RING_RES [mm] "KC00080BKP"
  round 2.2 / inner round 0 / far side round 2.2 hole 1.1 paste-2.403 mask+0: 1(0,2.3) 2(0,-2.3)
D12.0MM [mm] "KC00080BKP"
  oval 2.2x2.4 / inner round 0 / far side oval 2.2x2.4 hole 1.4 paste-2.603 mask+0: 1(-0.026,-0.045) 2(12,0)
D20.0mm [mil] "KC00080BKP"
  round 118 / inner round 0 / far side round 118 hole 59 paste-126 mask+0: 1(0,0) 2(0,787.4)
DIODE [mm] "KC00080BKP"
  rect 2x2.8 smd paste-3.003 mask+0: 1(0.381,-0.381) 2(4.881,-0.381)
DIP8 [mm] "KC00080BKP"
  rect 2x1.6 / inner round 0 / far side rect 2x1.6 hole 0.889 paste-2.203 mask+0: 1(0,0)
  oval 2x1.6 / inner round 0 / far side oval 2x1.6 hole 0.889 paste-2.203 mask+0: 2(0,-2.54) 3(0,-5.08) 4(0,-7.62) 5(8.7,-7.62) 6(8.7,-5.08) 7(8.7,-2.54) 8(8.7,0)
Discharge_tube_15.0mm [mm] "KC00080BKP"
  oval 2.489x2.5 / inner round 0 / far side oval 2.489x2.5 hole 1.3 paste-2.703 mask+0: 1(-0.003,-0.013) 2(14.999,0.013)
E2-6MM [mm] "KC00080BKP"
  oval 1.8x1.5 / inner round 0 / far side oval 1.8x1.5 hole 1 paste-2.003 mask+0: 1(0,-1.1) 2(0,1.1)
E2.5-6.3MM [mil] "KC00080BKP"
  oval 70x65 / inner round 0 / far side oval 70x65 hole 39.37 paste-78 mask+0: 1(0,50) 2(0,148.42)
E3.7-8.4MM [mm] "KC00080BKP"
  oval 2x1.8 / inner round 0 / far side oval 2x1.8 hole 1 paste-2.203 mask+0: 1(0,-1.8) 2(0,1.8)
FCSL110R010FER [mm] "KC00080BKP"
  rect 2.9x11.8 smd paste-12.003 mask+0: 1(2.6,0) 2(-2.6,0)
FP-SSOP5-IPC_A [mm] "KC00080BKP"
  rect 1.406x0.594 smd paste-1.406 mask+0: 1(-1.35,0.95)
  round 0.178 smd paste-0.178 mask+0: 2(-1.35,0) 3(-1.35,-0.95) 4(1.35,-0.95) 5(1.35,0.95)
FT-4-15C [mm] "KC00080BKP"
  round 3.4 / inner round 0 / far side round 3.4 hole 2.4 paste-3.603 mask+0: 1(9.993,-9) 2(9.993,9) 3(-9.993,-8.849) 4(-9.993,8.785)
FUSE30A/250VAC [mm] "KC00080BKP"
  round 2.54 / inner round 0 / far side round 2.54 hole 1.3 paste-2.743 mask+0: 1(-18.3,0.05) 2(18.4,-0.05)
HDR1X5H [mm] "KC00080BKP"
  rect 2.5x3.5 / inner round 0 / far side rect 2.5x3.5 hole 1.6 paste-3.703 mask+0: 1(0,0)
  round 0 hole 1.9 paste-1.9 mask+0: 2(4.05,0) 4(12,0)
  oval 2.5x3.5 / inner round 0 / far side oval 2.5x3.5 hole 1.9 paste-3.703 mask+0: 3(8.1,0) 5(15.9,0)
KKBYQ4_C [mil] "KC00080BKP"
  oval 120x94 / inner round 0 / far side oval 120x94 hole 47 paste-128 mask+0: 1(-296.5,236)
  oval 120x98 / inner round 0 / far side oval 120x98 hole 47 paste-128 mask+0: 2(-295.5,79) 5(295.5,-236) 6(296.5,-85.94) 7(296.5,79) 8(295.5,236)
  round 47.24 / inner round 0 / far side round 47.24 hole 47.24 paste-55.24 mask+0: 3(-291.38,-83.9)
LED-0805 [mm] "KC00080BKP"
  rect 1.3x1.3 smd paste-1.503 mask+0: 1(0,0) 2(2.489,0)
LQFP64_M [mm] "KC00080BKP"
  oval 2.5x0.3 smd paste-2.703 mask+0: 1(-5.8,3.75) 2(-5.8,3.25) 3(-5.8,2.75) 4(-5.8,2.25) 5(-5.8,1.75) 6(-5.8,1.25) 7(-5.8,0.75) 8(-5.8,0.25) 9(-5.8,-0.25) 10(-5.8,-0.75) 11(-5.8,-1.25) 12(-5.8,-1.75) 13(-5.8,-2.25) 14(-5.8,-2.75) 15(-5.8,-3.25) 16(-5.8,-3.75) 33(5.8,-3.75) 34(5.8,-3.25) 35(5.8,-2.75) 36(5.8,-2.25) 37(5.8,-1.75) 38(5.8,-1.25) 39(5.8,-0.75) 40(5.8,-0.25) 41(5.8,0.25) 42(5.8,0.75) 43(5.8,1.25) 44(5.8,1.75) 45(5.8,2.25) 46(5.8,2.75) 47(5.8,3.25) 48(5.8,3.75)
  oval 0.3x2.5 smd paste-2.703 mask+0: 17(-3.75,-5.8) 18(-3.25,-5.8) 19(-2.75,-5.8) 20(-2.25,-5.8) 21(-1.75,-5.8) 22(-1.25,-5.8) 23(-0.75,-5.8) 24(-0.25,-5.8) 25(0.25,-5.8) 26(0.75,-5.8) 27(1.25,-5.8) 28(1.75,-5.8) 29(2.25,-5.8) 30(2.75,-5.8) 31(3.25,-5.8) 32(3.75,-5.8) 49(3.75,5.8) 50(3.25,5.8) 51(2.75,5.8) 52(2.25,5.8) 53(1.75,5.8) 54(1.25,5.8) 55(0.75,5.8) 56(0.25,5.8) 57(-0.25,5.8) 58(-0.75,5.8) 59(-1.25,5.8) 60(-1.75,5.8) 61(-2.25,5.8) 62(-2.75,5.8) 63(-3.25,5.8) 64(-3.75,5.8)
MKP22MM [mm] "KC00080BKP"
  round 2 / inner round 0 / far side round 2 hole 1.3 paste-2.203 mask+0: 1(-11.303,0) 2(11.25,0)
P-SSOP30_C [mm] "KC00080BKP"
  oval 2.05x0.6 smd paste-2.253 mask+0: 1(-6.9,9) 2(-6.9,8) 3(-6.9,7) 4(-6.9,6) 5(-6.9,5) 6(-6.9,4) 7(-6.9,3) 8(-6.9,2) 9(-6.9,1) 10(-6.9,0) 11(-6.9,-1) 12(-6.9,-2) 13(-6.9,-3) 14(-6.9,-4) 15(-6.9,-5) 16(-6.9,-6) 17(-6.9,-7) 18(-6.9,-8) 19(-6.9,-9) 20(6.9,-9.3) 21(6.9,-6.6) 22(6.9,-5.6) 23(6.9,-2.9) 24(6.9,-1.9) 25(6.9,0.8) 26(6.9,1.8) 27(6.9,4.5) 28(6.9,5.5) 29(6.9,8.2) 30(6.9,9.2)
PAD4.0MM [mil] "KC00080BKP"
  round 155 / inner round 0 / far side round 155 hole 106.3 paste-163 mask+0: 1(0,0)
PAD250 [mil] "KC00080BKP"
  round 110 / inner round 0 / far side round 110 hole 47.24 paste-118 mask+0: 1(0,-100) 2(0,100)
PFC_INDUCTANCE_C [mm] "KC00080BKP"
  round 4 / inner round 0 / far side round 4 hole 2.4 paste-4.203 mask+0: 1(12.8,10.8) 2(5.2,10.8) 3(-12.8,10.8) 4(-12.8,-10.8) 5(-5.2,-10.8) 6(12.8,-10.8)
PTC-5.0MM [mil] "KC00080BKP"
  round 90 / inner round 0 / far side round 90 hole 39.37 paste-98 mask+0: 1(0,0) 2(197.56,0)
PTC__12X20_ [mm] "KC00080BKP"
  round 2.8 / inner round 0 / far side round 2.8 hole 1.8 paste-3.003 mask+0: 1(0,-4.9) 2(0,4.9)
R12.0mm [mm] "KC00080BKP"
  round 2.286 / inner round 0 / far side round 2.286 hole 1.2 paste-2.489 mask+0: 1(0,0)
  round 2 / inner round 0 / far side round 2 hole 1.2 paste-2.203 mask+0: 2(0,12)
R20.0MM [mm] "KC00080BKP"
  round 2.286 / inner round 0 / far side round 2.286 hole 1.2 paste-2.489 mask+0: 1(0,0)
  round 2 / inner round 0 / far side round 2 hole 1.2 paste-2.203 mask+0: 2(0,20)
RB0.8-10-36 [mm] "KC00080BKP"
  oval 4.5x5 / inner round 0 / far side oval 4.5x5 hole 2.5 paste-5.203 mask+0: 1(0,0) 2(10,0)
RC15.0+10.0_C [mm] "KC00080BKP"
  round 1.524 / inner round 0 / far side round 1.524 hole 1 paste-1.727 mask+0: 1(-7.5,0) 2(7.5,0) ""(-5,0) ""(5,0)
RY-2160 [mil] "KC00080BKP"
  round 130 / inner round 0 / far side round 130 hole 82.68 paste-138 mask+0: 1(545.08,280.81) 2(-541.54,279.23) 3(-376.19,-189.27) 4(466.33,-189.27)
RY-JZC-32F [mm] "KC00080BKP"
  round 1.778 / inner round 0 / far side round 1.778 hole 1.2 paste-1.981 mask+0: 1(9.1,14.05) 2(1.5,16.59)
  round 1.778 / inner round 0 / far side round 1.778 hole 1 paste-1.981 mask+0: 3(1.5,1.35) 4(9.1,1.35)
SMD_CAP_6.6_x_6.6 [mm] "KC00080BKP"
  rect 3.6x2 smd paste-3.803 mask+0: 1(-2.8,0) 2(2.8,0)
SMT-0603-C [mm] "KC00080BKP"
  rect 0.8x0.9 smd paste-1.103 mask+0: 1(-0.7,0) 2(0.7,0)
SMT-0603-R [mm] "KC00080BKP"
  rect 0.8x0.9 smd paste-1.103 mask+0: 1(-0.7,0) 2(0.7,0)
SMT-0805-C [mm] "KC00080BKP"
  rect 1.3x1.3 smd paste-1.503 mask+0: 1(0,0) 2(2.489,0)
SMT-0805-R [mm] "KC00080BKP"
  rect 1.3x1.3 smd paste-1.503 mask+0: 1(0,0) 2(2.489,0)
SMT-1206-R [mm] "KC00080BKP"
  rect 1.6x1.8 smd paste-2.003 mask+0: 1(-1.4,0) 2(1.4,0)
SMT-1210-R [mm] "KC00080BKP"
  rect 1.7x2.8 smd paste-3.003 mask+0: 1(-1.55,0) 2(1.55,0)
SOP16 [mil] "KC00080BKP"
  oval 25x80 smd paste-88 mask+0: 1(0,0) 2(50,0) 3(100,0) 4(150,0) 5(200,0) 6(250,0) 7(300,0) 8(350,0) 9(350,209.84) 10(300,209.84) 11(250,209.84) 12(200,209.84) 13(150,209.84) 14(100,209.84) 15(50,209.84) 16(0,209.84)
SOP-8 [mm] "KC00080BKP"
  oval 2.1x0.6 smd paste-2.303 mask+0: 1(-2.85,1.905) 2(-2.85,0.635) 3(-2.85,-0.635) 4(-2.85,-1.905) 5(2.85,-1.905) 6(2.85,-0.635) 7(2.85,0.635) 8(2.85,1.905)
SOP-8_-1 [mm] "KC00080BKP"
  oval 2.1x0.6 smd paste-2.303 mask+0: 1(-2.85,1.905) 2(-2.85,0.635) 3(-2.85,-0.635) 4(-2.85,-1.905) 7(2.85,0.635) 8(2.85,1.905)
  oval 2.1x0.5 smd paste-2.303 mask+0: 5(2.9,-2) 6(2.9,-0.6)
SOTFL50P160X60-5N [mm] "KC00080BKP"
  rect 0.8x0.35 smd paste-1.003 mask+0: 1(-0.675,0.5) 2(-0.675,0) 3(-0.675,-0.5) 4(0.675,-0.5) 5(0.675,0.5)
SSOP8 [mm] "KC00080BKP"
  round 0.178 smd paste-0.178 mask+0: 1(-1.975,0.975) 2(-1.975,0.325) 3(-1.975,-0.325) 4(-1.975,-0.975) 5(1.975,-0.975) 6(1.975,-0.325) 7(1.975,0.325) 8(1.975,0.975)
TESTPAD [mm] "KC00080BKP"
  round 1.6 / inner round 0 / far side round 1.6 hole 1 paste-1.803 mask+0: 1(0.04,0)
TK20A60W5_C [mm] "KC00080BKP"
  round 2.2 / inner round 0 / far side round 2.2 hole 1.2 paste-2.403 mask+0: 1(-2.54,1.024) 2(0,-1.524) 3(2.54,1.024)
TLP521 [mil] "KC00080BKP"
  round 60 / inner round 0 / far side round 65 hole 31.5 paste-73 mask+0: A(130,-30) C(130,-330) E(30,-330) K(30,-30)
TO220_heat_sink_C [mil] "KC00080BKP"
  oval 65x70 / inner round 0 / far side oval 65x70 hole 43.31 paste-78 mask+0: 1(98.93,-48.31) 2(0.51,-48.31) 3(-97.92,-48.31)
  oval 120x90 / inner round 0 / far side oval 120x90 hole 55.12 paste-128 mask+0: 4(-1.92,-246.3)
TO-3P_C [mil] "KC00080BKP"
  round 120 / inner round 0 / far side round 120 hole 59.06 paste-128 mask+0: 1(762.11,218.03) 2(762.11,3.03) 3(762.11,-211.97)
TRS24N65FB_C [mil] "KC00080BKP"
  round 120 / inner round 0 / far side round 120 hole 59.06 paste-128 mask+0: 1(762.13,218.03) 2(762.11,3.03) 3(762.11,-211.97)
VA [mil] "KC00080BKP"
  round 70 / inner round 0 / far side round 70 hole 47.24 paste-78 mask+0: 1(0,0) 2(283.63,-90.87)
XH2.54/2P [mm] "KC00080BKP"
  rect 1.5x1.5 / inner round 0 / far side rect 1.5x1.5 hole 0.9 paste-1.703 mask+0: 1(0,0)
  round 1.5 / inner round 0 / far side round 1.5 hole 0.9 paste-1.703 mask+0: 2(2.54,0)
XH2.54/4P [mm] "KC00080BKP"
  rect 1.5x1.5 / inner round 0 / far side rect 1.5x1.5 hole 0.9 paste-1.703 mask+0: 1(0,0)
  round 1.5 / inner round 0 / far side round 1.5 hole 0.9 paste-1.703 mask+0: 2(2.54,0) 3(5.08,0) 4(7.62,0)
XH2.54/5P [mm] "KC00080BKP"
  rect 1.5x1.5 / inner round 0 / far side rect 1.5x1.5 hole 0.9 paste-1.703 mask+0: 1(0,0)
  round 1.5 / inner round 0 / far side round 1.5 hole 0.9 paste-1.703 mask+0: 2(2.54,0) 3(5.08,0) 4(7.62,0) 5(10.16,0)
XH2.54/6P [mm] "KC00080BKP"
  rect 1.5x1.5 / inner round 0 / far side rect 1.5x1.5 hole 0.9 paste-1.703 mask+0: 1(0,0)
  round 1.5 / inner round 0 / far side round 1.5 hole 0.9 paste-1.703 mask+0: 2(2.54,0) 3(5.08,0) 4(7.62,0) 5(10.16,0) 6(12.7,0)

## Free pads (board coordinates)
  round 0.762 / inner round 0 / far side round 0.762 hole 0.381 paste-0.762 mask+0: ""(21.058,34.872) ""(21.079,38.866) ""(21.1,44.805) ""(21.1,50.725) ""(21.664,55.373) ""(22.262,27.032) ""(27.112,51.115) ""(27.741,21.373) ""(27.763,55.588) ""(28.636,37.653) ""(28.636,40.193) ""(30.414,36.51) ""(31.001,52.33) ""(31.303,53.909) ""(32.071,53.026) ""(35.661,21.269) ""(37.272,38.923) ""(37.908,48.932) ""(37.93,45.359) ""(37.967,44.076) ""(37.973,42.712) ""(37.995,41.485) ""(38.024,40.11) ""(38.239,95.779) ""(38.88,94.676) ""(40.296,53.386) ""(41.376,46.714) ""(41.971,44.13) ""(42.307,34.389) ""(42.513,40.658) ""(42.625,39.609) ""(43.767,28.682) ""(44.367,55.63) ""(44.482,41.59) ""(45.189,44.053) ""(45.908,21.397) ""(45.917,25.928) ""(52.203,34.535) ""(57.878,90.695) ""(58.354,34.478) ""(58.656,41.895) ""(58.735,90.695) ""(59.624,90.695) ""(59.646,42.53) ""(60.292,48.457) ""(60.741,42.53) ""(61.058,53.641) ""(61.632,43.038) ""(62.857,27.931) ""(62.946,43.546) ""(63.307,99.248) ""(63.772,25.732) ""(64.317,37.739) ""(66.113,58.257) ""(66.833,36.376) ""(66.956,34.176) ""(68.133,35.618) ""(68.26,47.305) ""(69.687,25.361) ""(70.113,28.652) ""(73.135,34.512) ""(75.372,34.478) ""(76.168,59.239) ""(76.769,26.223) ""(76.803,21.452) ""(77.699,59.746) ""(79.055,60.259) ""(80.325,21.397) ""(80.475,34.534) ""(80.895,39.051) ""(81.106,54.816) ""(81.926,51.161) ""(81.967,36.978) ""(82.737,36.311) ""(83.551,35.642) ""(84.008,28.89) ""(84.281,72.947) ""(84.954,21.559) ""(88.58,28.89) ""(88.595,33.67) ""(88.595,35.371) ""(88.595,36.663) ""(88.595,38.109) ""(88.67,25.81) ""(89.003,59.564) ""(89.22,21.43) ""(90.81,64.745) ""(90.834,63.961) ""(91.515,57.44) ""(92.501,64.341) ""(92.505,65.147) ""(93.895,82.351) ""(94.024,62.995) ""(94.965,78.418) ""(95.477,66.895) ""(96.97,66.875) ""(97.896,86.629) ""(98.403,76.402) ""(99.446,70.873) ""(99.611,66.795) ""(99.642,68.236) ""(99.661,65.418) ""(99.883,92.136) ""(100.051,79.165) ""(100.444,84.334) ""(102.385,95.539) ""(102.953,74.907) ""(103.705,72.706) ""(104.426,73.39) ""(104.907,70.734) ""(104.936,82.599) ""(105.217,95.565) ""(105.929,70.725) ""(106.283,89.983) ""(106.335,73.822) ""(107.046,78.718) ""(107.11,73.289) ""(107.137,77.174) ""(107.639,79.506) ""(107.777,90.362) ""(111.499,50.588) ""(111.642,48.099) ""(111.694,95.438) ""(112.327,50.596) ""(112.44,48.122) ""(112.851,68.781) ""(113.02,63.225) ""(113.576,69.379) ""(113.787,83.265) ""(113.863,91.056) ""(113.925,81.327) ""(114.232,63.211) ""(114.245,66.61) ""(114.305,68.048) ""(114.359,87.437) ""(114.487,83.976) ""(114.505,69.167) ""(114.506,91.891) ""(115.356,63.233) ""(115.36,87.519) ""(115.504,70.927) ""(115.751,66.202) ""(115.773,77.551) ""(116.388,88.026) ""(116.393,74.229) ""(116.647,84.008) ""(116.729,93.05) ""(117.54,95.594) ""(118.147,88.757) ""(119.08,89.081) ""(119.276,88.162) ""(119.94,77.312) ""(120.182,89.317) ""(120.457,73.848) ""(121.123,65.964) ""(121.191,91.719) ""(121.212,89.446) ""(121.624,88.601) ""(121.977,76.343) ""(122.017,87.718) ""(122.058,65.863) ""(122.083,95.437) ""(122.285,52.201) ""(122.408,90.795) ""(122.601,86.935) ""(122.616,70.927) ""(122.752,92.862) ""(122.82,85.882) ""(122.835,61.935) ""(123.417,52.182) ""(123.758,95.623) ""(123.911,65.923) ""(124.133,67.425) ""(124.578,89.788) ""(124.994,68.228) ""(125.157,65.823) ""(125.249,87.205) ""(126.078,53.283) ""(126.28,68.47) ""(126.92,66.526) ""(127.655,81.787) ""(127.709,84.974) ""(128.572,56.837) ""(128.877,70.723) ""(129.091,89.799) ""(129.983,69.848) ""(130.364,95.645) ""(131.897,71.882) ""(132.395,94.549) ""(132.977,72.246) ""(134.046,78.039) ""(134.046,83.627) ""(134.499,66.997) ""(135.255,94.355) ""(136.214,76.427) ""(137.557,70.597) ""(137.983,86.548) ""(137.992,95.712) ""(138.73,57.073) ""(138.912,94.967) ""(138.999,85.717) ""(139.634,89.215) ""(139.897,94.061) ""(140.241,66.828) ""(140.523,90.485) ""(140.7,93.158) ""(141.666,68.133) ""(142.428,53.274) ""(142.801,55.781) ""(142.809,61.529) ""(144.346,64.049) ""(144.396,85.32) ""(145.035,66.77) ""(145.348,79.916) ""(145.366,77.929) ""(145.366,81.977) ""(145.598,68.345) ""(145.611,85.049) ""(146.492,56.068) ""(146.709,72.274) ""(147.508,55.306) ""(147.522,71.548) ""(164.799,106.092) ""(165.183,107.708) ""(170.428,106.744) ""(170.545,114.621) ""(171.253,111.23) ""(172.789,81.977) ""(173.434,90.067) ""(173.924,105.217) ""(174.692,87.804) ""(177.158,85.649) ""(177.604,102.414) ""(179.113,87.071) ""(179.503,102.395) ""(179.639,108.138) ""(179.68,105.633) ""(179.815,114.263) ""(179.842,82.312) ""(180.09,91.02) ""(181.253,110.638) ""(181.268,82.257) ""(182.69,110.567) ""(183.182,101.216) ""(183.195,97.47) ""(183.356,98.756) ""(183.449,104.963) ""(183.99,59.269) ""(185.624,91.535) ""(186.082,106.186) ""(186.116,97.343) ""(189.801,68.519) ""(190.561,64.577) ""(190.561,86.675) ""(190.672,101.951) ""(192.252,92.157) ""(192.336,99.942) ""(192.545,68.338) ""(192.553,67.597) ""(194.752,101.026) ""(196.25,89.857) ""(199.188,105.13) ""(199.705,100.772) ""(200.22,104.049) ""(202.903,59.496) ""(205.255,89.446) ""(205.832,101.246) ""(206.69,92.39) ""(208.087,68.559) ""(209.275,64.897) ""(209.847,101.253) ""(209.851,97.491) ""(211.223,68.554) ""(211.226,67.742) ""(211.387,90.991) ""(212.913,100.905) ""(213.122,96.948) ""(213.732,97.42) ""(216.805,104.568) ""(218.678,108.144) ""(219.567,104.588) ""(220.131,91.776) ""(220.519,95.997) ""(221.377,99.107) ""(221.422,98.105) ""(221.442,58.948) ""(222.674,91.382) ""(224.806,103.298) ""(225.462,98.39) ""(225.466,99.4) ""(225.511,97.19) ""(225.776,106.822) ""(227.792,69.117) ""(228.053,94.244) ""(228.767,65.064)
  round 3 / inner round 0 / far side round 3 hole 3 unplated paste-3.203 mask+0: ""(23.271,23.306) ""(23.316,176.666) ""(111.106,43.537) ""(137.706,43.537) ""(226.375,23.302) ""(226.417,176.683)
  round 0.508 smd paste-0.508 mask+0: ""(24.064,46.797) ""(144.206,61.591)
  round 1.143 / inner round 0 / far side round 1.143 hole 0.61 paste-1.143 mask+0: ""(29.927,175.158) ""(30.967,168.732) ""(33.772,165.249) ""(47.57,133.632) ""(53.446,116.399) ""(60.367,121.42) ""(109.527,118.469) ""(109.58,119.856) ""(111.5,59.75) ""(113.9,61.576) ""(121.558,38.531) ""(122.655,38.475) ""(126.222,63.389) ""(126.287,112.498) ""(126.377,106.36) ""(126.377,107.837) ""(126.377,109.408) ""(126.377,110.94) ""(126.553,48.575) ""(127.951,106.36) ""(127.951,107.837) ""(127.951,109.408) ""(127.951,110.94) ""(129.41,67.234) ""(129.444,48.708) ""(129.526,106.36) ""(129.526,107.837) ""(129.526,109.408) ""(129.526,110.94) ""(130.335,58.583) ""(131.1,106.36) ""(131.1,107.837) ""(131.1,109.408) ""(131.1,110.94) ""(131.167,99.688) ""(131.996,97.439) ""(132.377,99.725) ""(132.675,106.36) ""(132.675,107.837) ""(132.675,109.408) ""(132.675,110.94) ""(133.35,97.431) ""(133.367,113.914) ""(134.173,106.36) ""(134.173,107.837) ""(134.173,109.408) ""(134.173,110.94) ""(134.173,112.456) ""(135.05,113.914) ""(135.824,106.36) ""(135.824,107.837) ""(135.824,109.408) ""(135.824,110.94) ""(135.824,112.456) ""(142.152,73.492) ""(145.136,74.008) ""(145.367,75.203) ""(146.184,76.733) ""(146.396,74.167) ""(146.731,75.583) ""(147.603,74.446) ""(171.484,102.315) ""(172.821,102.315) ""(172.957,97.267) ""(173.432,100.248) ""(174.657,100.219) ""(193.146,140.134) ""(197.35,139.025) ""(197.927,115.504) ""(200.34,115.504) ""(201.356,128.077) ""(201.356,131.125) ""(201.356,134.935) ""(201.483,118.552) ""(201.483,121.6) ""(201.483,125.029) ""(221.676,142.809) ""(227.518,156.398)
  round 0.254 smd paste-0.254 mask+0: ""(32.065,24.445) ""(40.701,33.97) ""(116.937,82.448) ""(137.59,88.618) ""(175.894,91.705) ""(175.981,84.807) ""(200.656,100.772)
  round 2.54 smd paste-2.54 mask+0: ""(62.307,176.87) ""(198.308,71.816) ""(216.85,71.8)
  round 2.54 smd far side paste-2.54 mask+0: ""(62.307,176.87)
  round 0.254 smd far side paste-0.254 mask+0: ""(84.784,141.512) ""(122.017,87.718) ""(168.32,60.526)
  round 1.27 smd far side paste-1.27 mask+0: ""(126.553,48.575)
  round 1.016 smd paste-1.016 mask+0: ""(127.49,64.656)
  round 1.524 / inner round 0 / far side round 1.524 hole 0.762 paste-1.727 mask+0: ""(147.45,83.373) ""(147.47,81.628) ""(147.507,80.014) ""(149.147,83.373) ""(149.203,81.628) ""(149.218,78.337) ""(150.845,83.373) ""(150.897,76.582) ""(150.911,78.346) ""(150.936,81.628) ""(151.016,80.014) ""(152.542,83.373) ""(152.653,76.572) ""(152.668,81.628) ""(152.751,78.293) ""(152.771,80.014) ""(154.239,83.373) ""(154.366,76.642) ""(154.401,81.628) ""(154.497,78.364) ""(154.525,80.014) ""(159.526,110.834) ""(159.526,112.381) ""(159.573,113.98) ""(160.376,109.591) ""(160.811,113.028) ""(160.822,114.777) ""(160.838,111.497) ""(161.478,108.519) ""(161.677,110.341) ""(161.987,113.633) ""(162.367,112.202) ""(162.748,109.535) ""(162.875,108.138) ""(163.002,110.932) ""(163.51,52.512) ""(163.51,54.036) ""(163.51,55.56) ""(163.51,57.084) ""(165.034,52.512) ""(165.034,54.036) ""(165.034,55.56) ""(165.034,56.957) ""(166.558,52.512) ""(166.558,54.036) ""(166.558,55.56) ""(166.558,57.084) ""(167.955,52.512) ""(167.955,54.036) ""(168.082,55.56) ""(168.082,57.084) ""(178.623,76.896) ""(178.623,78.547) ""(180.401,75.372) ""(180.401,76.896) ""(180.401,78.547) ""(180.528,69.784) ""(181.798,67.879) ""(182.043,76.203) ""(182.052,77.785) ""(182.052,79.436) ""(182.941,65.593) ""(183.523,78.888) ""(183.576,75.499) ""(183.703,77.15) ""(184.913,78.156) ""(200.299,70.176) ""(202.118,68.387) ""(202.372,66.101) ""(218.709,70.465) ""(220.307,68.864) ""(220.914,65.847) ""(223.196,35.223) ""(223.2,32.192) ""(223.2,33.716) ""(224.654,35.512) ""(224.703,33.97) ""(224.724,32.446) ""(226.123,35.79) ""(226.178,34.199) ""(226.248,32.7) ""(227.64,35.995) ""(227.797,32.761) ""(227.797,34.412)
  round 2.794 / inner round 0 / far side round 2.794 hole 7.854 unplated paste-7.854 mask+0: ""(179.525,35.321) ""(179.525,57.8) ""(198.321,35.321) ""(198.321,57.8) ""(216.863,35.321) ""(216.863,57.8)
  round 0.508 smd far side paste-0.508 mask+0: ""(183.449,104.963)
  round 2.794 / inner round 0 / far side round 2.794 hole 9 unplated paste-9 mask+0: ""(192.784,157.64)
  round 8.128 / inner round 0 / far side round 8.128 hole 9 unplated paste-9 mask+0: ""(210.246,115.25) ""(210.319,132.366)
